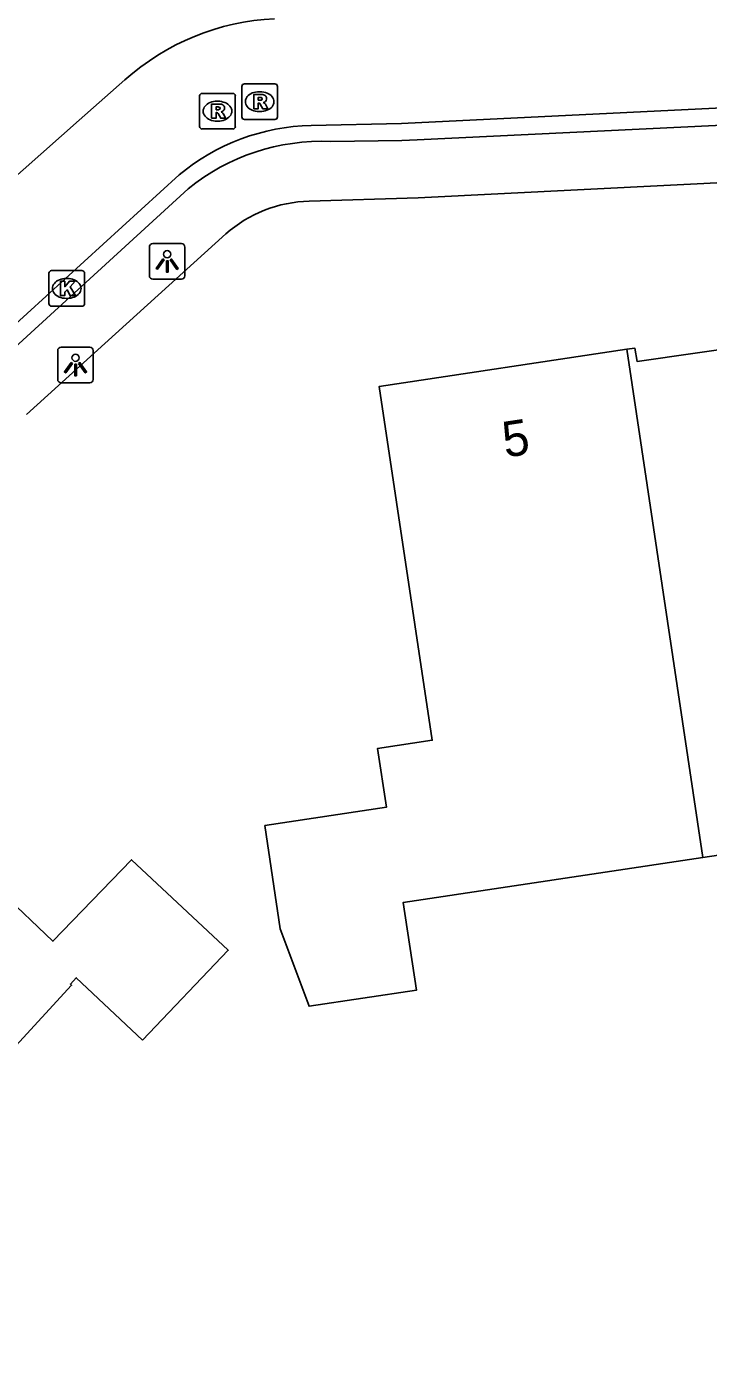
# Model space of a CAD drawing. Extents: x 162157 to 163165, y 378998 to 380775.
# Drawn here: x 162284.71 to 162303.85, y 380199.96 to 380237.07 of the extents above; entities that cross this region are included whole.
import ezdxf

# ---------------------------------------------------------------- set-up
doc = ezdxf.new("R2010")
doc.units = 0
for name, color, linetype in [('IMGEO_Kolk', 7, 'Continuous'), ('IMGEO_Lichtpunt', 7, 'Continuous'), ('IMGEO_Pand', 7, 'Continuous'), ('IMGEO_Pand_nummerreeks', 7, 'Continuous'), ('IMGEO_Rijbaan_lokaal_open', 7, 'Continuous'), ('IMGEO_Rioolput', 7, 'Continuous'), ('IMGEO_Voetpad_open', 7, 'Continuous')]:
    doc.layers.add(name, color=color, linetype=linetype)

msp = doc.modelspace()

# ---------------------------------------------------------------- linework, layer by layer
at = {"layer": 'IMGEO_Kolk'}
for p, q in [((162285.343, 380229.289), (162285.343, 380230.141)), ((162285.418, 380230.215), (162286.27, 380230.215)), ((162285.831, 380229.995), (162285.856, 380229.995)), ((162286.344, 380230.141), (162286.344, 380229.289)), ((162286.27, 380229.215), (162285.418, 380229.215)), ((162285.854, 380229.435), (162285.829, 380229.435))]:
    msp.add_line(p, q, dxfattribs=at)
for points in [[(162285.343, 380229.289), (162285.343, 380230.141)], [(162285.418, 380230.215), (162286.27, 380230.215)], [(162286.344, 380230.141), (162286.344, 380229.289)], [(162285.664, 380229.915), (162285.787, 380229.915), (162285.787, 380229.764), (162285.917, 380229.915), (162286.081, 380229.915), (162285.935, 380229.764), (162286.088, 380229.515), (162285.936, 380229.515), (162285.851, 380229.679), (162285.787, 380229.612), (162285.787, 380229.515), (162285.664, 380229.515), (162285.664, 380229.915)], [(162286.27, 380229.215), (162285.418, 380229.215)]]:
    msp.add_lwpolyline(points, dxfattribs=at)
for centre, start, end in [((162285.42, 380230.139), 91.552, 178.448), ((162285.42, 380230.139), 91.552, 178.448), ((162286.268, 380230.139), 1.552, 88.448), ((162286.268, 380230.139), 1.552, 88.448), ((162285.42, 380229.291), 181.552, 268.448), ((162285.42, 380229.291), 181.552, 268.448), ((162286.268, 380229.291), 271.552, 358.448), ((162286.268, 380229.291), 271.552, 358.448)]:
    msp.add_arc(centre, 0.0765, start, end, dxfattribs=at)
for centre, major_axis, ratio, start_param, end_param in [((162285.83, 380229.715), (-0.387, 0.002), 0.722429, 4.712389, 7.853982), ((162285.855, 380229.715), (-0.39, 0.002), 0.717154, 1.570796, 4.712389)]:
    msp.add_ellipse(centre, major_axis=major_axis, ratio=ratio, start_param=start_param, end_param=end_param, dxfattribs=at)
at = {"layer": 'IMGEO_Lichtpunt'}
for p, q in [((162288.161, 380230.877), (162288.161, 380230.07)), ((162288.161, 380230.877), (162288.161, 380230.07)), ((162289.063, 380230.972), (162288.255, 380230.972)), ((162289.063, 380230.972), (162288.255, 380230.972)), ((162289.157, 380230.07), (162289.157, 380230.877)), ((162289.157, 380230.07), (162289.157, 380230.877)), ((162288.255, 380229.976), (162289.063, 380229.976)), ((162288.255, 380229.976), (162289.063, 380229.976)), ((162286.492, 380228.064), (162285.684, 380228.064)), ((162286.492, 380228.064), (162285.684, 380228.064)), ((162285.59, 380227.969), (162285.59, 380227.162)), ((162285.59, 380227.969), (162285.59, 380227.162)), ((162286.586, 380227.162), (162286.586, 380227.969)), ((162286.586, 380227.162), (162286.586, 380227.969)), ((162285.684, 380227.068), (162286.492, 380227.068)), ((162285.684, 380227.068), (162286.492, 380227.068))]:
    msp.add_line(p, q, dxfattribs=at)
for points in [[(162288.535, 380230.541), (162288.574, 380230.513), (162288.386, 380230.251), (162288.348, 380230.278), (162288.535, 380230.541)], [(162288.637, 380230.493), (162288.684, 380230.493), (162288.684, 380230.171), (162288.637, 380230.171), (162288.637, 380230.493)], [(162288.747, 380230.513), (162288.785, 380230.54), (162288.972, 380230.278), (162288.933, 380230.25), (162288.747, 380230.513)], [(162285.964, 380227.633), (162286.003, 380227.605), (162285.815, 380227.343), (162285.777, 380227.37), (162285.964, 380227.633)], [(162286.066, 380227.585), (162286.113, 380227.585), (162286.113, 380227.263), (162286.066, 380227.263), (162286.066, 380227.585)], [(162286.176, 380227.605), (162286.214, 380227.632), (162286.401, 380227.37), (162286.362, 380227.342), (162286.176, 380227.605)]]:
    msp.add_lwpolyline(points, dxfattribs=at)
for centre in [(162288.66, 380230.675), (162286.089, 380227.767)]:
    msp.add_circle(centre, 0.0994, dxfattribs=at)
for centre, start, end in [((162288.255, 380230.877), 90, 180), ((162288.255, 380230.877), 90, 180), ((162289.063, 380230.877), 0, 90), ((162289.063, 380230.877), 0, 90), ((162288.255, 380230.07), 180, 270), ((162288.255, 380230.07), 180, 270), ((162289.063, 380230.07), 270, 0), ((162289.063, 380230.07), 270, 360), ((162285.684, 380227.969), 90, 180), ((162285.684, 380227.969), 90, 180), ((162286.492, 380227.969), 0, 90), ((162286.492, 380227.969), 0, 90), ((162285.684, 380227.162), 180, 270), ((162285.684, 380227.162), 180, 270), ((162286.492, 380227.162), 270, 0), ((162286.492, 380227.162), 270, 360)]:
    msp.add_arc(centre, 0.0946, start, end, dxfattribs=at)
at = {"layer": 'IMGEO_Pand'}
for points in [[(162301.556, 380228.006), (162301.776, 380228.039), (162301.848, 380227.66), (162308.548, 380228.625), (162309.976, 380219.109), (162311.451, 380219.324), (162312.1, 380214.998), (162303.688, 380213.74)], [(162303.688, 380213.74), (162295.276, 380212.481), (162295.656, 380210.025), (162292.642, 380209.57), (162291.834, 380211.745), (162291.4, 380214.642), (162294.812, 380215.154), (162294.564, 380216.805), (162296.097, 380217.035), (162294.609, 380226.964), (162301.556, 380228.006)], [(162303.688, 380213.74), (162301.556, 380228.006)], [(162287.964, 380208.617), (162286.11, 380210.368), (162285.945, 380210.193), (162285.981, 380210.159), (162281.905, 380205.735), (162284.012, 380203.711), (162280.491, 380199.993), (162280.463, 380199.963), (162278.276, 380202.027), (162278.039, 380201.776), (162272.574, 380206.942), (162275.069, 380209.661), (162273.946, 380210.722), (162279.323, 380216.412), (162283.63, 380212.335), (162284.022, 380212.762), (162285.455, 380211.393), (162287.661, 380213.679), (162290.372, 380211.142), (162287.964, 380208.617)]]:
    msp.add_lwpolyline(points, dxfattribs=at)
at = {"layer": 'IMGEO_Rijbaan_lokaal_open'}
for points in [[(162292.702, 380234.286), (162295.236, 380234.347), (162346.564, 380236.852)], [(162287.476, 380235.57), (162286.193, 380234.44), (162281.47, 380230.257)], [(162293.252, 380233.837), (162295.241, 380233.863), (162295.669, 380233.884), (162328.568, 380235.47)], [(162283.128, 380227.55), (162289.001, 380232.898)], [(162283.613, 380227.351), (162289.253, 380232.511)]]:
    msp.add_lwpolyline(points, dxfattribs=at)
for centre, radius, start, end in [((162291.989, 380230.507), 6.783, 92.7164, 131.7135), ((162292.811, 380228.367), 5.92, 91.0558, 130.0597), ((162292.994, 380227.923), 5.92, 87.4984, 129.1908)]:
    msp.add_arc(centre, radius, start, end, dxfattribs=at)
at = {"layer": 'IMGEO_Rioolput'}
for p, q in [((162289.571, 380234.263), (162289.571, 380235.115)), ((162289.646, 380235.189), (162290.498, 380235.189)), ((162290.572, 380235.115), (162290.572, 380234.263)), ((162290.753, 380234.53), (162290.753, 380235.382)), ((162290.828, 380235.456), (162291.68, 380235.456)), ((162291.241, 380235.236), (162291.266, 380235.236)), ((162291.754, 380235.382), (162291.754, 380234.53)), ((162290.059, 380234.969), (162290.084, 380234.969)), ((162290.082, 380234.409), (162290.057, 380234.409)), ((162291.68, 380234.456), (162290.828, 380234.456)), ((162291.264, 380234.676), (162291.239, 380234.676)), ((162290.498, 380234.189), (162289.646, 380234.189))]:
    msp.add_line(p, q, dxfattribs=at)
for points in [[(162289.571, 380234.263), (162289.571, 380235.115)], [(162289.646, 380235.189), (162290.498, 380235.189)], [(162290.572, 380235.115), (162290.572, 380234.263)], [(162290.753, 380234.53), (162290.753, 380235.382)], [(162290.828, 380235.456), (162291.68, 380235.456)], [(162291.342, 380235.154), (162291.09, 380235.156), (162291.09, 380234.756)], [(162291.754, 380235.382), (162291.754, 380234.53)], [(162290.16, 380234.887), (162289.908, 380234.889), (162289.908, 380234.489)], [(162290.086, 380234.808), (162290.032, 380234.808), (162290.032, 380234.727)], [(162291.09, 380234.756), (162291.214, 380234.756), (162291.214, 380234.918), (162291.225, 380234.918)], [(162291.268, 380235.075), (162291.214, 380235.075), (162291.214, 380234.994)], [(162291.214, 380234.994), (162291.266, 380234.994)], [(162291.272, 380234.889), (162291.343, 380234.756), (162291.483, 380234.756), (162291.418, 380234.882)], [(162289.908, 380234.489), (162290.032, 380234.489), (162290.032, 380234.651), (162290.043, 380234.651)], [(162290.032, 380234.727), (162290.084, 380234.727)], [(162290.09, 380234.622), (162290.161, 380234.489), (162290.301, 380234.489), (162290.236, 380234.615)], [(162291.68, 380234.456), (162290.828, 380234.456)], [(162290.498, 380234.189), (162289.646, 380234.189)]]:
    msp.add_lwpolyline(points, dxfattribs=at)
for centre, radius, start, end in [((162289.648, 380235.113), 0.0765, 91.552, 178.448), ((162289.648, 380235.113), 0.0765, 91.552, 178.448), ((162290.496, 380235.113), 0.0765, 1.552, 88.448), ((162290.496, 380235.113), 0.0765, 1.552, 88.448), ((162290.83, 380235.38), 0.0765, 91.552, 178.448), ((162290.83, 380235.38), 0.0765, 91.552, 178.448), ((162291.341, 380235.044), 0.109, 350.3612, 89.416), ((162291.678, 380235.38), 0.0765, 1.552, 88.448), ((162291.678, 380235.38), 0.0765, 1.552, 88.448), ((162290.092, 380234.712), 0.0964, 77.0061, 93.1865), ((162290.106, 380234.769), 0.0378, 276.6634, 79.6772), ((162290.159, 380234.777), 0.109, 350.3612, 89.416), ((162290.157, 380234.777), 0.112, 277.5842, 350.9817), ((162291.224, 380234.865), 0.0533, 26.0293, 88.6989), ((162291.25, 380235.183), 0.19, 274.7715, 282.9687), ((162291.274, 380234.979), 0.0964, 77.0061, 93.1865), ((162291.288, 380235.036), 0.0378, 276.6634, 79.6772), ((162291.339, 380235.044), 0.112, 277.5842, 350.9817), ((162291.323, 380234.829), 0.108, 29.5134, 73.7905), ((162290.042, 380234.598), 0.0533, 26.0293, 88.6989), ((162290.068, 380234.916), 0.19, 274.7715, 282.9687), ((162290.141, 380234.562), 0.108, 29.5134, 73.7905), ((162290.83, 380234.532), 0.0765, 181.552, 268.448), ((162290.83, 380234.532), 0.0765, 181.552, 268.448), ((162291.678, 380234.532), 0.0765, 271.552, 358.448), ((162291.678, 380234.532), 0.0765, 271.552, 358.448), ((162289.648, 380234.265), 0.0765, 181.552, 268.448), ((162289.648, 380234.265), 0.0765, 181.552, 268.448), ((162290.496, 380234.265), 0.0765, 271.552, 358.448), ((162290.496, 380234.265), 0.0765, 271.552, 358.448)]:
    msp.add_arc(centre, radius, start, end, dxfattribs=at)
for centre, major_axis, ratio, start_param, end_param in [((162291.24, 380234.956), (-0.387, 0.002), 0.722429, 4.712389, 7.853982), ((162291.265, 380234.956), (-0.39, 0.002), 0.717154, 1.570796, 4.712389), ((162290.058, 380234.689), (-0.387, 0.002), 0.722429, 4.712389, 7.853982), ((162290.083, 380234.689), (-0.39, 0.002), 0.717154, 1.570796, 4.712389)]:
    msp.add_ellipse(centre, major_axis=major_axis, ratio=ratio, start_param=start_param, end_param=end_param, dxfattribs=at)
at = {"layer": 'IMGEO_Voetpad_open'}
for points in [[(162328.663, 380233.968), (162321.403, 380233.547), (162295.698, 380232.255), (162292.644, 380232.161)], [(162290.304, 380231.243), (162284.713, 380226.18)]]:
    msp.add_lwpolyline(points, dxfattribs=at)
msp.add_arc((162292.717, 380228.535), 3.627, 91.1469, 131.6941, dxfattribs=at)

# ---------------------------------------------------------------- texts
at = {"layer": 'IMGEO_Pand_nummerreeks'}
msp.add_text('5', height=1, rotation=8.5313, dxfattribs=at).set_placement((162298.142, 380224.966))

doc.saveas('drawing.dxf')
